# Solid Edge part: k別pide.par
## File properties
Title: käepide
Author: Stella-Marii
Template: Iso Metric Part.par
Last saved by: Stella-Marii
Revision: 7
Application: Solid Edge
Density: 1050,000 kg/m^3
Accuracy: 0,990
Username: Stella-Marii
Document Number: 18
Material: Polyurethene
Face Style: Blue
Fill Style: ANSI34(Plastic)
Virtual Style: ANSI34(Plastic)
Grouping: Non-metals\Plastics
LibraryName: Materials
Coef. of Thermal Exp: 9e-05
Thermal Conductivity: 0.2
Specific Heat: 0.0
Modulus of Elasticity: 0.0
Poisson's Ratio: 0.4
Yield Stress: 0.0
Ultimate Stress: 0.0
Elongation: 0.0
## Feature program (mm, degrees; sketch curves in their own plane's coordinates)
sketch for "unnamed Protrusion 1" plane through (0, 0, 0) normal (1, 0, 0) x-axis (0, 1, 0)
  circle centre (0, 0) radius 15
extrude "unnamed Protrusion 1" add finite 130 along +normal
sketch for "unnamed Cutout 1" plane through (130, 0, 0) normal (1, 0, 0) x-axis (0, 1, 0)
  circle centre (0, 0) radius 12.5
extrude "unnamed Cutout 1" cut finite 2 along -normal
fillet "Round_2" radius 2  Radii2 = 1 mm
sketch for "ExtrudedProtrusion_2" plane through (0, 0, 0) normal (0, 0, 1) x-axis (1, 0, 0)
  circle centre (12.0278, 0) radius 1
extrude "ExtrudedProtrusion_2" add finite 16 along +normal
fillet "Round_3" radius 1
pattern "unnamed Pattern 1" of "Round_3", "ExtrudedProtrusion_2"
pattern "unnamed Pattern 2"
pattern "unnamed Pattern 3" of "unnamed Pattern 2", "Round_3", "ExtrudedProtrusion_2"
pattern "unnamed Pattern 4"
sketch for "ExtrudedCutout_2" plane through (0, 0, 0) normal (-1, 0, 0) x-axis (0, -1, 0)
  circle centre (0, 0) radius 13
extrude "ExtrudedCutout_2" cut finite 124.869 along -normal
sketch for "unnamed RevolvedProtrusion 1" plane through (0, 0, 0) normal (0, -1, 0) x-axis (1, 0, 0)
revolve "unnamed RevolvedProtrusion 1" add finite 360 deg
fillet "Round_4" radius 3
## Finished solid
Body 1: solid body, 311 faces, 410 edges, 200 vertices.
  Faces by surface: cylinder 203, sphere 100, plane 4, torus 3, cone 1
  Edges by curve: circle 210, intersection 200
Bounding box of the edges (mm; curved faces can reach further): 130.000 x 38.050 x 38.050, from (0, -19.0249, -19.0249) to (130, 19.0249, 19.0249).
Cylindrical faces by radius (mm): R1 x200, R12.5 x1, R13 x1, R15 x1
Conical faces (half-angle, radius in mm at the cone's reference point): 21.9241 deg R15 x1
Toroidal faces (ring radius, tube radius in mm): R11.5 r1 x1, R13 r2 x1, R18 r3 x1
Spherical faces by radius (mm): R1 x100
Planar faces by outward normal: +x 2, -x 2
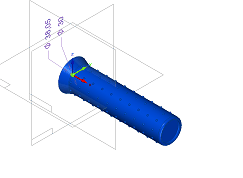
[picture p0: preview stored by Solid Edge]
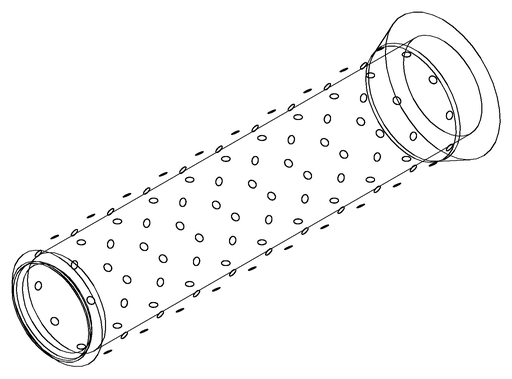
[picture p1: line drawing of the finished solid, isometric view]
